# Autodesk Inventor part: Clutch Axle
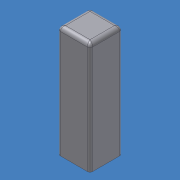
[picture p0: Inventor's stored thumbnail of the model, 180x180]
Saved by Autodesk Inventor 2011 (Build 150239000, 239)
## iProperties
Created: 2007-08
Part Number: Clutch Axle
Material: Steel
Document SubType Name: Modeling
Density: 7.85 g/cm^3
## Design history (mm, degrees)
feature "Base1"
body "Solid1"
